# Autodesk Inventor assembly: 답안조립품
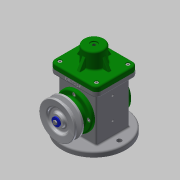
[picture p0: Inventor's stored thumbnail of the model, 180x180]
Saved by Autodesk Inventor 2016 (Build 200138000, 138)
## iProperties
Created: 2018-10
Part Number: 답안조립품
Document SubType Name: Assembly
Designer: MIRAE
Author: MIRAE
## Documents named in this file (18)
- C:\Users\MIRAE\Desktop\481007V1052\답안조립품.iam
- C:\Users\MIRAE\Desktop\481007V1052\본체.ipt
- C:\Users\MIRAE\Desktop\481007V1052\덮개.ipt
- C:\Users\MIRAE\Desktop\481007V1052\뒤커버.ipt
- C:\Users\MIRAE\Desktop\481007V1052\링크.ipt
- C:\Users\MIRAE\Desktop\481007V1052\베어링 17 x 40 x 12.ipt
- C:\Users\MIRAE\Desktop\481007V1052\볼트 M4 x 8.ipt
- C:\Users\MIRAE\Desktop\481007V1052\볼트 M4 x 10.ipt
- C:\Users\MIRAE\Desktop\481007V1052\슬라이더.ipt
- C:\Users\MIRAE\Desktop\481007V1052\앞커버.ipt
- C:\Users\MIRAE\Desktop\481007V1052\오일 실 17 30 8.ipt
- C:\Users\MIRAE\Desktop\481007V1052\와셔 4x16.ipt
- C:\Users\MIRAE\Desktop\481007V1052\클레비스 핀 6 x 22.ipt
- 클레비스 핀 6 x 22.ipt
- C:\Users\MIRAE\Desktop\481007V1052\키 4 x 4 x 12.ipt
- C:\Users\MIRAE\Desktop\481007V1052\편심축.ipt
- C:\Users\MIRAE\Desktop\481007V1052\E-링.ipt
- C:\Users\MIRAE\Desktop\481007V1052\V-벨트풀리.ipt
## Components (2 placed, 2 different names)
1. E-링:1
2. V-벨트풀리:1
